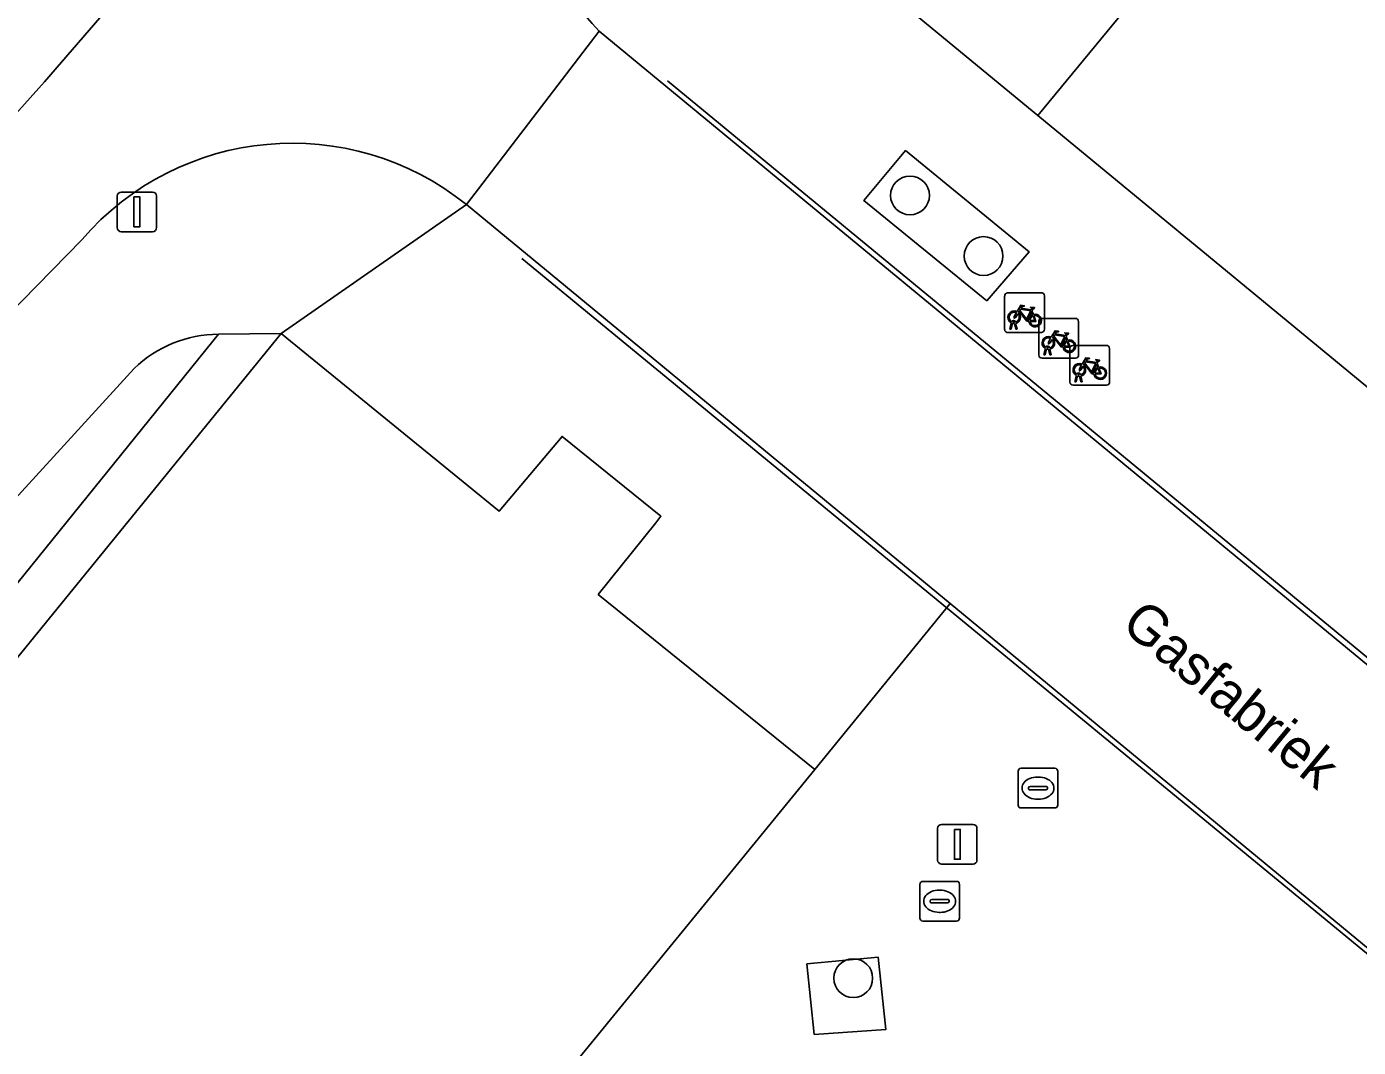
# Model space of a CAD drawing. Extents: x 161772 to 163126, y 383092 to 383917.
# Drawn here: x 161942.28 to 161975.82, y 383268.94 to 383294.65 of the extents above; entities that cross this region are included whole.
import ezdxf

# ---------------------------------------------------------------- set-up
doc = ezdxf.new("R2010")
doc.units = 0
for name, color, linetype in [('IMGEO_Berm_open', 7, 'Continuous'), ('IMGEO_Boom', 7, 'Continuous'), ('IMGEO_Brandkraan', 7, 'Continuous'), ('IMGEO_Fietsenrek', 7, 'Continuous'), ('IMGEO_Groenvoorziening', 7, 'Continuous'), ('IMGEO_Kolk', 7, 'Continuous'), ('IMGEO_Lichtmast', 7, 'Continuous'), ('IMGEO_Lijnafwatering', 7, 'Continuous'), ('IMGEO_Openbare_ruimte_label', 7, 'Continuous'), ('IMGEO_Pand', 7, 'Continuous'), ('IMGEO_Rijbaan_lokaal_gesloten', 7, 'Continuous'), ('IMGEO_Rijbaan_lokaal_open', 7, 'Continuous'), ('IMGEO_Voetpad_gesloten', 7, 'Continuous'), ('IMGEO_Voetpad_halfverhard', 7, 'Continuous'), ('IMGEO_Voetpad_open', 7, 'Continuous')]:
    doc.layers.add(name, color=color, linetype=linetype)

msp = doc.modelspace()

# ---------------------------------------------------------------- linework, layer by layer
at = {"layer": 'IMGEO_Berm_open'}
msp.add_lwpolyline([(161936.941, 383286.844), (161937.725, 383287.694), (161938.545, 383288.593), (161942.733, 383293.261), (161946.965, 383298.168), (161951.858, 383304.076), (161955.895, 383309.039), (161956.93, 383310.332), (161955.277, 383311.727), (161955.257, 383311.744), (161958.985, 383316.324), (161961.426, 383319.531), (161961.064, 383319.803), (161964.615, 383324.66), (161964.958, 383324.39), (161966.144, 383326.081)], dxfattribs=at)
at = {"layer": 'IMGEO_Boom'}
for centre in [(161964.528, 383290.399), (161966.38, 383288.872), (161963.098, 383270.682)]:
    msp.add_circle(centre, 0.489, dxfattribs=at)
at = {"layer": 'IMGEO_Brandkraan'}
for p, q in [((161967.324, 383275.969), (161968.176, 383275.969)), ((161967.249, 383275.043), (161967.249, 383275.895)), ((161967.737, 383275.749), (161967.762, 383275.749)), ((161968.25, 383275.895), (161968.25, 383275.043)), ((161967.508, 383275.463), (161967.508, 383275.475)), ((161967.946, 383275.426), (161967.548, 383275.426)), ((161967.551, 383275.512), (161967.949, 383275.512)), ((161967.992, 383275.475), (161967.992, 383275.463)), ((161968.176, 383274.969), (161967.324, 383274.969)), ((161967.76, 383275.189), (161967.735, 383275.189))]:
    msp.add_line(p, q, dxfattribs=at)
for points in [[(161967.324, 383275.969), (161968.176, 383275.969)], [(161967.249, 383275.043), (161967.249, 383275.895)], [(161968.25, 383275.895), (161968.25, 383275.043)], [(161968.176, 383274.969), (161967.324, 383274.969)]]:
    msp.add_lwpolyline(points, dxfattribs=at)
for centre, radius, start, end in [((161967.326, 383275.893), 0.0765, 91.552, 178.448), ((161967.326, 383275.893), 0.0765, 91.552, 178.448), ((161968.174, 383275.893), 0.0765, 1.552, 88.448), ((161968.174, 383275.893), 0.0765, 1.552, 88.448), ((161967.548, 383275.472), 0.0403, 85.8775, 175.7526), ((161967.545, 383275.462), 0.0366, 178.938, 274.7102), ((161967.949, 383275.469), 0.043, 264.8664, 352.4533), ((161967.953, 383275.474), 0.0386, 1.7309, 96.639), ((161967.326, 383275.045), 0.0765, 181.552, 268.448), ((161967.326, 383275.045), 0.0765, 181.552, 268.448), ((161968.174, 383275.045), 0.0765, 271.552, 358.448), ((161968.174, 383275.045), 0.0765, 271.552, 358.448)]:
    msp.add_arc(centre, radius, start, end, dxfattribs=at)
for centre, major_axis, ratio, start_param, end_param in [((161967.736, 383275.469), (-0.387, 0.002), 0.722429, 4.712389, 7.853982), ((161967.761, 383275.469), (-0.39, 0.002), 0.717154, 1.570796, 4.712389)]:
    msp.add_ellipse(centre, major_axis=major_axis, ratio=ratio, start_param=start_param, end_param=end_param, dxfattribs=at)
at = {"layer": 'IMGEO_Fietsenrek'}
for p, q in [((161966.911, 383287.021), (161966.911, 383287.862)), ((161966.911, 383287.862), (161966.911, 383287.021)), ((161966.986, 383287.946), (161967.827, 383287.946)), ((161967.827, 383287.946), (161966.986, 383287.946)), ((161967.911, 383287.871), (161967.911, 383287.03)), ((161967.911, 383287.03), (161967.911, 383287.871)), ((161967.598, 383287.495), (161967.634, 383287.4)), ((161967.038, 383287.03), (161967.077, 383287.19)), ((161967.072, 383287.03), (161967.038, 383287.03)), ((161967.107, 383287.178), (161967.072, 383287.03)), ((161967.149, 383287.202), (161967.148, 383287.206)), ((161967.19, 383287.03), (161967.156, 383287.172)), ((161967.18, 383287.213), (161967.181, 383287.206)), ((161967.188, 383287.176), (161967.223, 383287.03)), ((161967.223, 383287.03), (161967.19, 383287.03)), ((161967.771, 383286.375), (161967.771, 383287.216)), ((161967.771, 383287.216), (161967.771, 383286.375)), ((161967.846, 383287.3), (161968.687, 383287.3)), ((161968.687, 383287.3), (161967.846, 383287.3)), ((161968.771, 383287.225), (161968.771, 383286.384)), ((161968.771, 383286.384), (161968.771, 383287.225)), ((161967.836, 383286.946), (161966.995, 383286.946)), ((161966.995, 383286.946), (161967.836, 383286.946)), ((161968.458, 383286.849), (161968.494, 383286.754)), ((161967.898, 383286.384), (161967.937, 383286.544)), ((161967.932, 383286.384), (161967.898, 383286.384)), ((161967.967, 383286.532), (161967.932, 383286.384)), ((161968.009, 383286.556), (161968.008, 383286.56)), ((161968.05, 383286.384), (161968.016, 383286.526)), ((161968.04, 383286.567), (161968.041, 383286.56)), ((161968.048, 383286.53), (161968.083, 383286.384)), ((161968.083, 383286.384), (161968.05, 383286.384)), ((161968.551, 383285.696), (161968.551, 383286.537)), ((161968.551, 383286.537), (161968.551, 383285.696)), ((161968.626, 383286.621), (161969.467, 383286.621)), ((161969.467, 383286.621), (161968.626, 383286.621)), ((161969.551, 383286.546), (161969.551, 383285.705)), ((161969.551, 383285.705), (161969.551, 383286.546)), ((161968.696, 383286.3), (161967.855, 383286.3)), ((161967.855, 383286.3), (161968.696, 383286.3)), ((161969.238, 383286.17), (161969.274, 383286.075)), ((161968.678, 383285.705), (161968.717, 383285.865)), ((161968.712, 383285.705), (161968.678, 383285.705)), ((161968.747, 383285.853), (161968.712, 383285.705)), ((161968.789, 383285.877), (161968.788, 383285.881)), ((161968.83, 383285.705), (161968.796, 383285.847)), ((161968.82, 383285.888), (161968.821, 383285.881)), ((161968.828, 383285.851), (161968.863, 383285.705)), ((161968.863, 383285.705), (161968.83, 383285.705)), ((161969.476, 383285.621), (161968.635, 383285.621)), ((161968.635, 383285.621), (161969.476, 383285.621))]:
    msp.add_line(p, q, dxfattribs=at)
for points in [[(161967.245, 383287.42), (161967.193, 383287.33), (161967.153, 383287.305), (161967.154, 383287.352), (161967.209, 383287.446)], [(161967.224, 383287.472), (161967.319, 383287.636), (161967.405, 383287.622), (161967.407, 383287.613), (161967.351, 383287.602), (161967.324, 383287.557), (161967.58, 383287.516)], [(161967.52, 383287.228), (161967.47, 383287.228), (161967.279, 383287.479), (161967.26, 383287.447)], [(161967.567, 383287.491), (161967.31, 383287.532), (161967.293, 383287.503), (161967.46, 383287.283), (161967.567, 383287.491)], [(161967.615, 383287.393), (161967.585, 383287.47), (161967.476, 383287.252), (161967.519, 383287.252)], [(161967.549, 383287.252), (161967.669, 383287.251), (161967.625, 383287.365)], [(161967.645, 383287.372), (161967.7, 383287.227), (161967.55, 383287.227)], [(161967.58, 383287.516), (161967.605, 383287.565), (161967.599, 383287.569), (161967.576, 383287.573), (161967.564, 383287.58), (161967.563, 383287.583), (161967.565, 383287.588), (161967.66, 383287.573), (161967.662, 383287.563), (161967.652, 383287.55), (161967.64, 383287.544), (161967.626, 383287.55), (161967.598, 383287.495)], [(161968.105, 383286.774), (161968.053, 383286.684), (161968.013, 383286.659), (161968.014, 383286.706), (161968.069, 383286.8)], [(161968.084, 383286.826), (161968.179, 383286.99), (161968.265, 383286.976), (161968.267, 383286.967), (161968.211, 383286.956), (161968.184, 383286.911), (161968.44, 383286.87)], [(161968.38, 383286.582), (161968.33, 383286.582), (161968.139, 383286.833), (161968.12, 383286.801)], [(161968.427, 383286.845), (161968.17, 383286.886), (161968.153, 383286.857), (161968.32, 383286.637), (161968.427, 383286.845)], [(161968.475, 383286.747), (161968.445, 383286.824), (161968.336, 383286.606), (161968.379, 383286.606)], [(161968.409, 383286.606), (161968.529, 383286.605), (161968.485, 383286.719)], [(161968.505, 383286.726), (161968.56, 383286.581), (161968.41, 383286.581)], [(161968.44, 383286.87), (161968.465, 383286.919), (161968.459, 383286.923), (161968.436, 383286.927), (161968.424, 383286.934), (161968.423, 383286.937), (161968.425, 383286.942), (161968.52, 383286.927), (161968.522, 383286.917), (161968.512, 383286.904), (161968.5, 383286.898), (161968.486, 383286.904), (161968.458, 383286.849)], [(161968.885, 383286.095), (161968.833, 383286.005), (161968.793, 383285.98), (161968.794, 383286.027), (161968.849, 383286.121)], [(161968.864, 383286.147), (161968.959, 383286.311), (161969.045, 383286.297), (161969.047, 383286.288), (161968.991, 383286.277), (161968.964, 383286.232), (161969.22, 383286.191)], [(161969.16, 383285.903), (161969.11, 383285.903), (161968.919, 383286.154), (161968.9, 383286.122)], [(161969.207, 383286.166), (161968.95, 383286.207), (161968.933, 383286.178), (161969.1, 383285.958), (161969.207, 383286.166)], [(161969.255, 383286.068), (161969.225, 383286.145), (161969.116, 383285.927), (161969.159, 383285.927)], [(161969.189, 383285.927), (161969.309, 383285.926), (161969.265, 383286.04)], [(161969.285, 383286.047), (161969.34, 383285.902), (161969.19, 383285.902)], [(161969.22, 383286.191), (161969.245, 383286.24), (161969.239, 383286.244), (161969.216, 383286.248), (161969.204, 383286.255), (161969.203, 383286.258), (161969.205, 383286.263), (161969.3, 383286.248), (161969.302, 383286.238), (161969.292, 383286.225), (161969.28, 383286.219), (161969.266, 383286.225), (161969.238, 383286.17)]]:
    msp.add_lwpolyline(points, dxfattribs=at)
for centre, radius, start, end in [((161966.989, 383287.868), 0.0779, 92.4484, 184.2845), ((161966.989, 383287.868), 0.0779, 92.4484, 184.2845), ((161967.833, 383287.868), 0.0779, 2.4484, 94.2845), ((161967.833, 383287.868), 0.0779, 2.4484, 94.2845), ((161967.151, 383287.331), 0.159, 62.6766, 242.1369), ((161967.151, 383287.331), 0.129, 63.3192, 238.903), ((161967.151, 383287.331), 0.129, 283.6043, 43.4302), ((161967.151, 383287.331), 0.159, 283.5766, 46.6042), ((161967.678, 383287.247), 0.159, 113.3408, 178.3217), ((161967.678, 383287.247), 0.159, 187.0065, 105.7708), ((161967.678, 383287.247), 0.129, 113.923, 177.9556), ((161967.678, 383287.247), 0.129, 188.6715, 104.5883), ((161966.989, 383287.024), 0.0779, 182.4484, 274.2845), ((161966.989, 383287.024), 0.0779, 182.4484, 274.2845), ((161967.131, 383287.202), 0.0499, 12.8025, 158.6934), ((161967.151, 383287.331), 0.159, 253.9967, 271.7867), ((161967.131, 383287.202), 0.0174, 12.8025, 163.4502), ((161967.151, 383287.331), 0.129, 253.415, 269.0204), ((161967.849, 383287.222), 0.0779, 92.4484, 184.2845), ((161967.849, 383287.222), 0.0779, 92.4484, 184.2845), ((161967.833, 383287.024), 0.0779, 272.4484, 4.2845), ((161967.833, 383287.024), 0.0779, 272.4484, 4.2845), ((161968.693, 383287.222), 0.0779, 2.4484, 94.2845), ((161968.693, 383287.222), 0.0779, 2.4484, 94.2845), ((161968.011, 383286.685), 0.159, 62.6766, 242.1369), ((161968.011, 383286.685), 0.129, 63.3192, 238.903), ((161968.011, 383286.685), 0.129, 283.6043, 43.4302), ((161968.011, 383286.685), 0.159, 283.5766, 46.6042), ((161968.538, 383286.601), 0.159, 113.3408, 178.3217), ((161968.538, 383286.601), 0.159, 187.0065, 105.7708), ((161968.538, 383286.601), 0.129, 113.923, 177.9556), ((161968.538, 383286.601), 0.129, 188.6715, 104.5883), ((161967.849, 383286.378), 0.0779, 182.4484, 274.2845), ((161967.849, 383286.378), 0.0779, 182.4484, 274.2845), ((161967.991, 383286.556), 0.0499, 12.8025, 158.6934), ((161968.011, 383286.685), 0.159, 253.9967, 271.7867), ((161967.991, 383286.556), 0.0174, 12.8025, 163.4502), ((161968.011, 383286.685), 0.129, 253.415, 269.0204), ((161968.629, 383286.543), 0.0779, 92.4484, 184.2845), ((161968.629, 383286.543), 0.0779, 92.4484, 184.2845), ((161968.693, 383286.378), 0.0779, 272.4484, 4.2845), ((161968.693, 383286.378), 0.0779, 272.4484, 4.2845), ((161969.473, 383286.543), 0.0779, 2.4484, 94.2845), ((161969.473, 383286.543), 0.0779, 2.4484, 94.2845), ((161968.791, 383286.006), 0.159, 62.6766, 242.1369), ((161968.791, 383286.006), 0.129, 63.3192, 238.903), ((161968.791, 383286.006), 0.129, 283.6043, 43.4302), ((161968.791, 383286.006), 0.159, 283.5766, 46.6042), ((161969.318, 383285.922), 0.159, 113.3408, 178.3217), ((161969.318, 383285.922), 0.159, 187.0065, 105.7708), ((161969.318, 383285.922), 0.129, 113.923, 177.9556), ((161969.318, 383285.922), 0.129, 188.6715, 104.5883), ((161968.629, 383285.699), 0.0779, 182.4484, 274.2845), ((161968.629, 383285.699), 0.0779, 182.4484, 274.2845), ((161968.771, 383285.877), 0.0499, 12.8025, 158.6934), ((161968.791, 383286.006), 0.159, 253.9967, 271.7867), ((161968.771, 383285.877), 0.0174, 12.8025, 163.4502), ((161968.791, 383286.006), 0.129, 253.415, 269.0204), ((161969.473, 383285.699), 0.0779, 272.4484, 4.2845), ((161969.473, 383285.699), 0.0779, 272.4484, 4.2845)]:
    msp.add_arc(centre, radius, start, end, dxfattribs=at)
at = {"layer": 'IMGEO_Groenvoorziening'}
for points in [[(161966.464, 383287.742), (161967.524, 383288.979), (161964.415, 383291.531), (161963.364, 383290.273)], [(161962.111, 383269.265), (161963.915, 383269.387), (161963.725, 383271.211), (161961.933, 383271.041)]]:
    msp.add_lwpolyline(points, close=True, dxfattribs=at)
for points in [[(161920.997, 383254.575), (161919.034, 383256.173), (161924.881, 383263.332), (161926.722, 383261.652), (161947.115, 383286.904)], [(161944.99, 383286.04), (161914.219, 383252.347), (161915.758, 383251.09), (161917.095, 383249.921), (161920.997, 383254.575)]]:
    msp.add_lwpolyline(points, dxfattribs=at)
msp.add_arc((161947.137, 383283.805), 3.099, 90.4051, 133.847, dxfattribs=at)
at = {"layer": 'IMGEO_Kolk'}
for p, q in [((161964.774, 383272.193), (161964.774, 383273.045)), ((161964.849, 383273.119), (161965.701, 383273.119)), ((161965.775, 383273.045), (161965.775, 383272.193)), ((161965.033, 383272.613), (161965.033, 383272.625)), ((161965.076, 383272.662), (161965.474, 383272.662)), ((161965.262, 383272.899), (161965.287, 383272.899)), ((161965.517, 383272.625), (161965.517, 383272.613)), ((161965.471, 383272.576), (161965.073, 383272.576)), ((161965.285, 383272.339), (161965.26, 383272.339)), ((161965.701, 383272.119), (161964.849, 383272.119))]:
    msp.add_line(p, q, dxfattribs=at)
for points in [[(161964.774, 383272.193), (161964.774, 383273.045)], [(161964.849, 383273.119), (161965.701, 383273.119)], [(161965.775, 383273.045), (161965.775, 383272.193)], [(161965.701, 383272.119), (161964.849, 383272.119)]]:
    msp.add_lwpolyline(points, dxfattribs=at)
for centre, radius, start, end in [((161964.851, 383273.043), 0.0765, 91.552, 178.448), ((161964.851, 383273.043), 0.0765, 91.552, 178.448), ((161965.699, 383273.043), 0.0765, 1.552, 88.448), ((161965.699, 383273.043), 0.0765, 1.552, 88.448), ((161965.073, 383272.622), 0.0403, 85.8775, 175.7526), ((161965.07, 383272.612), 0.0366, 178.938, 274.7102), ((161965.474, 383272.619), 0.043, 264.8664, 352.4533), ((161965.478, 383272.624), 0.0386, 1.7309, 96.639), ((161964.851, 383272.195), 0.0765, 181.552, 268.448), ((161964.851, 383272.195), 0.0765, 181.552, 268.448), ((161965.699, 383272.195), 0.0765, 271.552, 358.448), ((161965.699, 383272.195), 0.0765, 271.552, 358.448)]:
    msp.add_arc(centre, radius, start, end, dxfattribs=at)
for centre, major_axis, ratio, start_param, end_param in [((161965.261, 383272.619), (-0.387, 0.002), 0.722429, 4.712389, 7.853982), ((161965.286, 383272.619), (-0.39, 0.002), 0.717154, 1.570796, 4.712389)]:
    msp.add_ellipse(centre, major_axis=major_axis, ratio=ratio, start_param=start_param, end_param=end_param, dxfattribs=at)
at = {"layer": 'IMGEO_Lichtmast'}
for p, q in [((161944.567, 383289.585), (161944.567, 383290.385)), ((161944.567, 383290.385), (161944.567, 383289.585)), ((161944.667, 383290.485), (161945.457, 383290.485)), ((161945.457, 383290.485), (161944.667, 383290.485)), ((161945.557, 383290.385), (161945.557, 383289.585)), ((161945.557, 383289.585), (161945.557, 383290.385)), ((161945.457, 383289.485), (161944.667, 383289.485)), ((161944.667, 383289.485), (161945.457, 383289.485)), ((161965.224, 383273.654), (161965.224, 383274.454)), ((161965.224, 383274.454), (161965.224, 383273.654)), ((161965.324, 383274.554), (161966.114, 383274.554)), ((161966.114, 383274.554), (161965.324, 383274.554)), ((161966.214, 383274.454), (161966.214, 383273.654)), ((161966.214, 383273.654), (161966.214, 383274.454)), ((161966.114, 383273.554), (161965.324, 383273.554)), ((161965.324, 383273.554), (161966.114, 383273.554))]:
    msp.add_line(p, q, dxfattribs=at)
for points in [[(161944.987, 383290.36), (161945.137, 383290.36), (161945.137, 383289.61), (161944.987, 383289.61), (161944.987, 383290.36)], [(161965.644, 383274.429), (161965.794, 383274.429), (161965.794, 383273.679), (161965.644, 383273.679), (161965.644, 383274.429)]]:
    msp.add_lwpolyline(points, dxfattribs=at)
for centre, start, end in [((161944.667, 383290.385), 90, 180), ((161944.667, 383290.385), 90, 180), ((161945.457, 383290.385), 0, 90), ((161945.457, 383290.385), 360, 90), ((161944.667, 383289.585), 180, 270), ((161944.667, 383289.585), 180, 270), ((161945.457, 383289.585), 270, 0), ((161945.457, 383289.585), 270, 0), ((161965.324, 383274.454), 90, 180), ((161965.324, 383274.454), 90, 180), ((161966.114, 383274.454), 0, 90), ((161966.114, 383274.454), 360, 90), ((161965.324, 383273.654), 180, 270), ((161965.324, 383273.654), 180, 270), ((161966.114, 383273.654), 270, 0), ((161966.114, 383273.654), 270, 0)]:
    msp.add_arc(centre, 0.1, start, end, dxfattribs=at)
at = {"layer": 'IMGEO_Lijnafwatering'}
for points in [[(161958.423, 383293.285), (161970.38, 383283.427)], [(161954.753, 383288.814), (161968.869, 383277.196)], [(161970.38, 383283.427), (161982.337, 383273.569)], [(161968.869, 383277.196), (161982.984, 383265.577)]]:
    msp.add_lwpolyline(points, dxfattribs=at)
at = {"layer": 'IMGEO_Pand'}
for points in [[(161974.85, 383301.031), (161969.361, 383305.552), (161967.005, 383302.695), (161963.945, 383305.221), (161959.192, 383299.463), (161967.744, 383292.413)], [(161987.446, 383295.992), (161987.81, 383296.45), (161977.847, 383304.666), (161974.85, 383301.031), (161967.744, 383292.413), (161977.726, 383284.185), (161982.568, 383290.067)]]:
    msp.add_lwpolyline(points, close=True, dxfattribs=at)
msp.add_lwpolyline([(161955.86, 383268.264), (161962.128, 383275.94), (161960.12, 383277.564), (161956.679, 383280.347), (161958.125, 383282.154), (161958.256, 383282.318), (161955.767, 383284.327), (161955.635, 383284.17), (161954.187, 383282.446), (161950.745, 383285.25), (161948.835, 383286.806), (161948.692, 383286.922), (161926.928, 383260.179)], dxfattribs=at)
at = {"layer": 'IMGEO_Rijbaan_lokaal_gesloten'}
for points in [[(161956.302, 383304.313), (161960.136, 383308.977), (161960.862, 383309.86), (161958.255, 383311.968), (161956.93, 383310.332), (161955.895, 383309.039), (161951.858, 383304.076), (161946.965, 383298.168), (161942.733, 383293.261), (161938.545, 383288.593), (161941.028, 383286.586), (161943.672, 383289.284)], [(161953.358, 383290.171), (161956.7, 383294.535)]]:
    msp.add_lwpolyline(points, dxfattribs=at)
for centre, radius, start, end in [((161962.124, 383299.656), 7.459, 191.0593, 223.3554), ((161948.974, 383284.718), 6.997, 51.2028, 139.2618)]:
    msp.add_arc(centre, radius, start, end, dxfattribs=at)
at = {"layer": 'IMGEO_Rijbaan_lokaal_open'}
for points in [[(161982.816, 383272.991), (161980.385, 383274.991), (161956.7, 383294.535), (161953.358, 383290.171), (161965.539, 383280.118), (161976.98, 383270.676), (162068.256, 383195.442), (162072.024, 383199.58), (162068.652, 383202.355), (162022.469, 383240.368), (162022.186, 383240.601)], [(161962.111, 383269.265), (161961.933, 383271.041), (161963.725, 383271.211), (161963.915, 383269.387)]]:
    msp.add_lwpolyline(points, close=True, dxfattribs=at)
msp.add_lwpolyline([(162054.895, 383187.865), (162058.675, 383184.763), (162059.171, 383185.317), (162057.611, 383186.767), (162058.979, 383188.263), (162060.56, 383186.888), (162066.195, 383193.13), (162067.57, 383194.688), (162068.256, 383195.442), (161976.98, 383270.676), (161965.539, 383280.118), (161962.128, 383275.94), (161955.86, 383268.264), (161962.269, 383262.995), (161962.168, 383262.726), (161966.806, 383258.778), (161967.104, 383258.925), (161971.077, 383255.833), (162035.261, 383203.214), (162035.951, 383202.874)], dxfattribs=at)
at = {"layer": 'IMGEO_Voetpad_gesloten'}
msp.add_lwpolyline([(161953.358, 383290.171), (161948.692, 383286.922), (161948.835, 383286.806), (161950.745, 383285.25), (161954.187, 383282.446), (161955.635, 383284.17), (161955.767, 383284.327), (161958.256, 383282.318), (161958.125, 383282.154), (161956.679, 383280.347), (161960.12, 383277.564), (161962.128, 383275.94), (161965.539, 383280.118)], close=True, dxfattribs=at)
at = {"layer": 'IMGEO_Voetpad_halfverhard'}
msp.add_lwpolyline([(161948.692, 383286.922), (161947.115, 383286.904), (161926.722, 383261.652), (161924.881, 383263.332), (161919.034, 383256.173), (161920.997, 383254.575), (161917.095, 383249.921), (161916.403, 383249.095), (161917.31, 383248.385), (161918.629, 383250), (161920.31, 383252.058), (161922.56, 383254.822), (161922.433, 383255.394), (161922.368, 383256.269), (161922.513, 383257.114), (161922.87, 383257.998), (161923.38, 383258.622), (161923.996, 383259.376), (161924.808, 383259.886), (161925.396, 383260.247), (161926.113, 383260.316), (161926.928, 383260.179)], close=True, dxfattribs=at)
at = {"layer": 'IMGEO_Voetpad_open'}
for points in [[(161977.726, 383284.185), (161967.744, 383292.413), (161959.192, 383299.463), (161963.945, 383305.221), (161966.298, 383308.075), (161969.617, 383312.103), (161973.219, 383316.411), (161974.112, 383315.664), (161981.734, 383309.38)], [(161956.7, 383294.535), (161980.385, 383274.991), (161982.816, 383272.991), (161986.243, 383277.164), (161977.726, 383284.185)], [(161947.115, 383286.904), (161948.692, 383286.922), (161953.358, 383290.171)], [(161943.672, 383289.284), (161941.028, 383286.586), (161938.996, 383284.148), (161925.176, 383268.972), (161894.115, 383235.022), (161890.056, 383230.375)], [(161889.361, 383224.53), (161893.362, 383229.411), (161895.999, 383232.397), (161910.307, 383248.064), (161914.219, 383252.347), (161944.99, 383286.04)]]:
    msp.add_lwpolyline(points, dxfattribs=at)
msp.add_lwpolyline([(161966.464, 383287.742), (161963.364, 383290.273), (161964.415, 383291.531), (161967.524, 383288.979)], close=True, dxfattribs=at)
for centre, radius, start, end in [((161962.124, 383299.656), 7.459, 191.0593, 223.3554), ((161948.974, 383284.718), 6.997, 51.2028, 139.2618), ((161947.137, 383283.805), 3.099, 90.4051, 133.847)]:
    msp.add_arc(centre, radius, start, end, dxfattribs=at)

# ---------------------------------------------------------------- texts
at = {"layer": 'IMGEO_Openbare_ruimte_label'}
msp.add_text('Gasfabriek', height=1, rotation=320.4365, dxfattribs=at).set_placement((161969.804, 383279.516))

doc.saveas('drawing.dxf')
